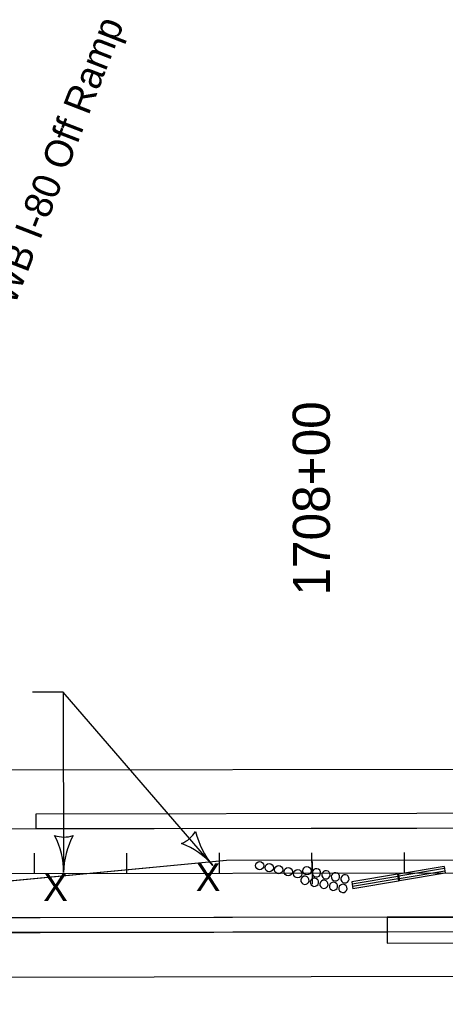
# Model space of a CAD drawing. Extents: x 16513048 to 16518780, y 7009856 to 7010869.
# Drawn here: x 16515461.8 to 16515576.9, y 7010324.9 to 7010588 of the extents above; entities that cross this region are included whole.
import ezdxf

# ---------------------------------------------------------------- set-up
doc = ezdxf.new("R2010")
doc.units = 0
for name, color, linetype in [('Dimensions', 7, 'Continuous'), ('DisCLMLORPoints', 7, 'Continuous'), ('dsnCellElements', 7, 'Continuous'), ('dsnNonPlotable', 7, 'Continuous'), ('EdgeShoulder', 7, 'Continuous'), ('Level 2', 7, 'Continuous'), ('PavementMarking', 7, 'Continuous'), ('Shape', 7, 'Continuous'), ('SheetBorder', 7, 'Continuous'), ('tdCoTitleBlock', 7, 'Continuous')]:
    doc.layers.add(name, color=color, linetype=linetype)

msp = doc.modelspace()

# ---------------------------------------------------------------- linework, layer by layer
at = {"layer": 'DisCLMLORPoints'}
for centre in [(16515526.66, 7010359.22), (16515529.22, 7010358.67), (16515531.79, 7010358.12), (16515539.42, 7010357.84), (16515539.42, 7010357.84), (16515534.36, 7010357.58), (16515536.93, 7010357.03)]:
    msp.add_circle(centre, 1.12, dxfattribs=at)
for centre, start, end in [((16515538.88, 7010355.27), 352.9741, 172.9741), ((16515541.99, 7010357.29), 172.9741, 352.9741), ((16515541.99, 7010357.29), 352.9741, 172.9741), ((16515544.56, 7010356.75), 172.9741, 352.9741), ((16515544.56, 7010356.75), 352.9741, 172.9741), ((16515547.12, 7010356.2), 172.9741, 352.9741), ((16515547.12, 7010356.2), 352.9741, 172.9741), ((16515549.69, 7010355.65), 352.9741, 172.9741), ((16515538.88, 7010355.27), 172.9741, 352.9741), ((16515541.44, 7010354.73), 172.9741, 352.9741), ((16515541.44, 7010354.73), 352.9741, 172.9741), ((16515544.01, 7010354.18), 352.9741, 172.9741), ((16515544.01, 7010354.18), 172.9741, 352.9741), ((16515546.58, 7010353.63), 172.9741, 352.9741), ((16515546.58, 7010353.63), 352.9741, 172.9741), ((16515549.14, 7010353.08), 352.9741, 172.9741), ((16515549.69, 7010355.65), 172.9741, 352.9741), ((16515549.14, 7010353.08), 172.9741, 352.9741)]:
    msp.add_arc(centre, 1.12, start, end, dxfattribs=at)
at = {"layer": 'dsnCellElements'}
for p, q in [((16515576.49, 7010359), (16515564.16, 7010356.94)), ((16515576.49, 7010359), (16515576.8, 7010357.15)), ((16515563.85, 7010356.89), (16515551.52, 7010354.82)), ((16515563.95, 7010356.3), (16515551.62, 7010354.23)), ((16515563.85, 7010356.89), (16515564.16, 7010355.04)), ((16515564.16, 7010356.94), (16515564.47, 7010355.09)), ((16515576.59, 7010358.41), (16515564.26, 7010356.35)), ((16515576.7, 7010357.74), (16515564.37, 7010355.68)), ((16515576.8, 7010357.15), (16515564.47, 7010355.09)), ((16515551.52, 7010354.82), (16515551.83, 7010352.98)), ((16515564.06, 7010355.63), (16515551.73, 7010353.57)), ((16515564.16, 7010355.04), (16515551.83, 7010352.98))]:
    msp.add_line(p, q, dxfattribs=at)
for centre, radius, start, end in [((16515473.79, 7010375.19), 8.22, 251.9296, 287.3963), ((16515452.4, 7010357.47), 21.28, 359.6629, 27.7354), ((16515494.96, 7010357.22), 21.28, 151.5904, 179.6629), ((16515502.34, 7010372.78), 8.22, 293.0217, 328.4884), ((16515530.11, 7010373.16), 21.28, 192.6825, 220.755), ((16515497.87, 7010345.37), 21.28, 40.755, 68.8275)]:
    msp.add_arc(centre, radius, start, end, dxfattribs=at)
at = {"layer": 'dsnNonPlotable'}
for p, q in [((16513050.27, 7010352.91), (16516699.62, 7010359.27)), ((16513050.32, 7010324.91), (16515740.86, 7010329.6))]:
    msp.add_line(p, q, dxfattribs=at)
for points in [[(16513050.22, 7010380.91), (16516699.59, 7010387.27), (16518770.65, 7010388.94)], [(16518770.66, 7010372.94), (16516699.61, 7010371.27), (16513050.25, 7010364.91)], [(16515602.66, 7010360.74), (16515517.66, 7010360.59), (16515353.41, 7010344.93)], [(16518770.68, 7010348.94), (16516699.64, 7010347.27), (16513050.29, 7010340.91)], [(16518770.69, 7010344.94), (16516699.64, 7010343.27), (16513050.3, 7010336.91)]]:
    msp.add_lwpolyline(points, dxfattribs=at)
at = {"layer": 'EdgeShoulder'}
for p, q in [((16515466.18, 7010373.12), (16515466.19, 7010369.23)), ((16515561.07, 7010345.29), (16515624.43, 7010345.4)), ((16515561.07, 7010345.29), (16515561.08, 7010338.29)), ((16515561.08, 7010338.29), (16515586.59, 7010338.33))]:
    msp.add_line(p, q, dxfattribs=at)
msp.add_lwpolyline([(16515466.19, 7010369.23), (16515672.02, 7010369.48), (16515672.01, 7010373.48)], dxfattribs=at)
at = {"layer": 'Level 2'}
for p, q in [((16515473.6, 7010406.13), (16515465.23, 7010406.12)), ((16515473.6, 7010406.13), (16515473.68, 7010357.35)), ((16515513.99, 7010359.26), (16515473.6, 7010406.13))]:
    msp.add_line(p, q, dxfattribs=at)
at = {"layer": 'PavementMarking'}
msp.add_lwpolyline([(16515602.66, 7010360.74), (16515517.66, 7010360.59), (16515352.69, 7010344.93)], dxfattribs=at)
at = {"layer": 'Shape'}
for points in [[(16515466.18, 7010373.12), (16515466.19, 7010369.23), (16515672.02, 7010369.48), (16515672.01, 7010373.48)], [(16515561.07, 7010345.29), (16515420.4, 7010345.04), (16515420.41, 7010341.04), (16515561.08, 7010341.29), (16515561.08, 7010338.29), (16515586.59, 7010338.33), (16515631.25, 7010340.24), (16515672.07, 7010340.32), (16515672.06, 7010345.48), (16515637.06, 7010345.42), (16515637.04, 7010358.42), (16515627.04, 7010358.4), (16515627.06, 7010345.4)]]:
    msp.add_lwpolyline(points, close=True, dxfattribs=at)
at = {"layer": 'SheetBorder'}
for p, q in [((16515465.79, 7010357.12), (16515465.78, 7010362.58)), ((16515490.79, 7010357.17), (16515490.78, 7010362.63)), ((16515515.79, 7010357.21), (16515515.78, 7010362.67)), ((16515565.79, 7010357.3), (16515565.78, 7010362.76)), ((16515540.79, 7010360.31), (16515540.8, 7010354.19))]:
    msp.add_line(p, q, dxfattribs=at)
at = {"layer": 'tdCoTitleBlock'}
msp.add_line((16515540.79, 7010357.25), (16515540.78, 7010362.71), dxfattribs=at)

# ---------------------------------------------------------------- texts
at = {"layer": 'Dimensions'}
msp.add_text('WB I-80 Off Ramp', height=7.5, rotation=68.7814, dxfattribs=at).set_placement((16515460.41, 7010510.45))
at = {"layer": 'Level 2'}
for p in [(16515509.37, 7010352.35), (16515468.14, 7010349.63)]:
    msp.add_text('X', height=7.51, dxfattribs=at).set_placement(p)
at = {"layer": 'SheetBorder'}
msp.add_text('1708+00', height=10.02, rotation=90.0999, dxfattribs=at).set_placement((16515545.67, 7010432.26))

doc.saveas('drawing.dxf')
